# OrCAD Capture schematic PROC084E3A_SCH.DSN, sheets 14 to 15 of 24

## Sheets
14 10. PRG0 GB_ETHERNET RGMII 2: size C; title: PRG0 GB_ETHERNET RGMII 2
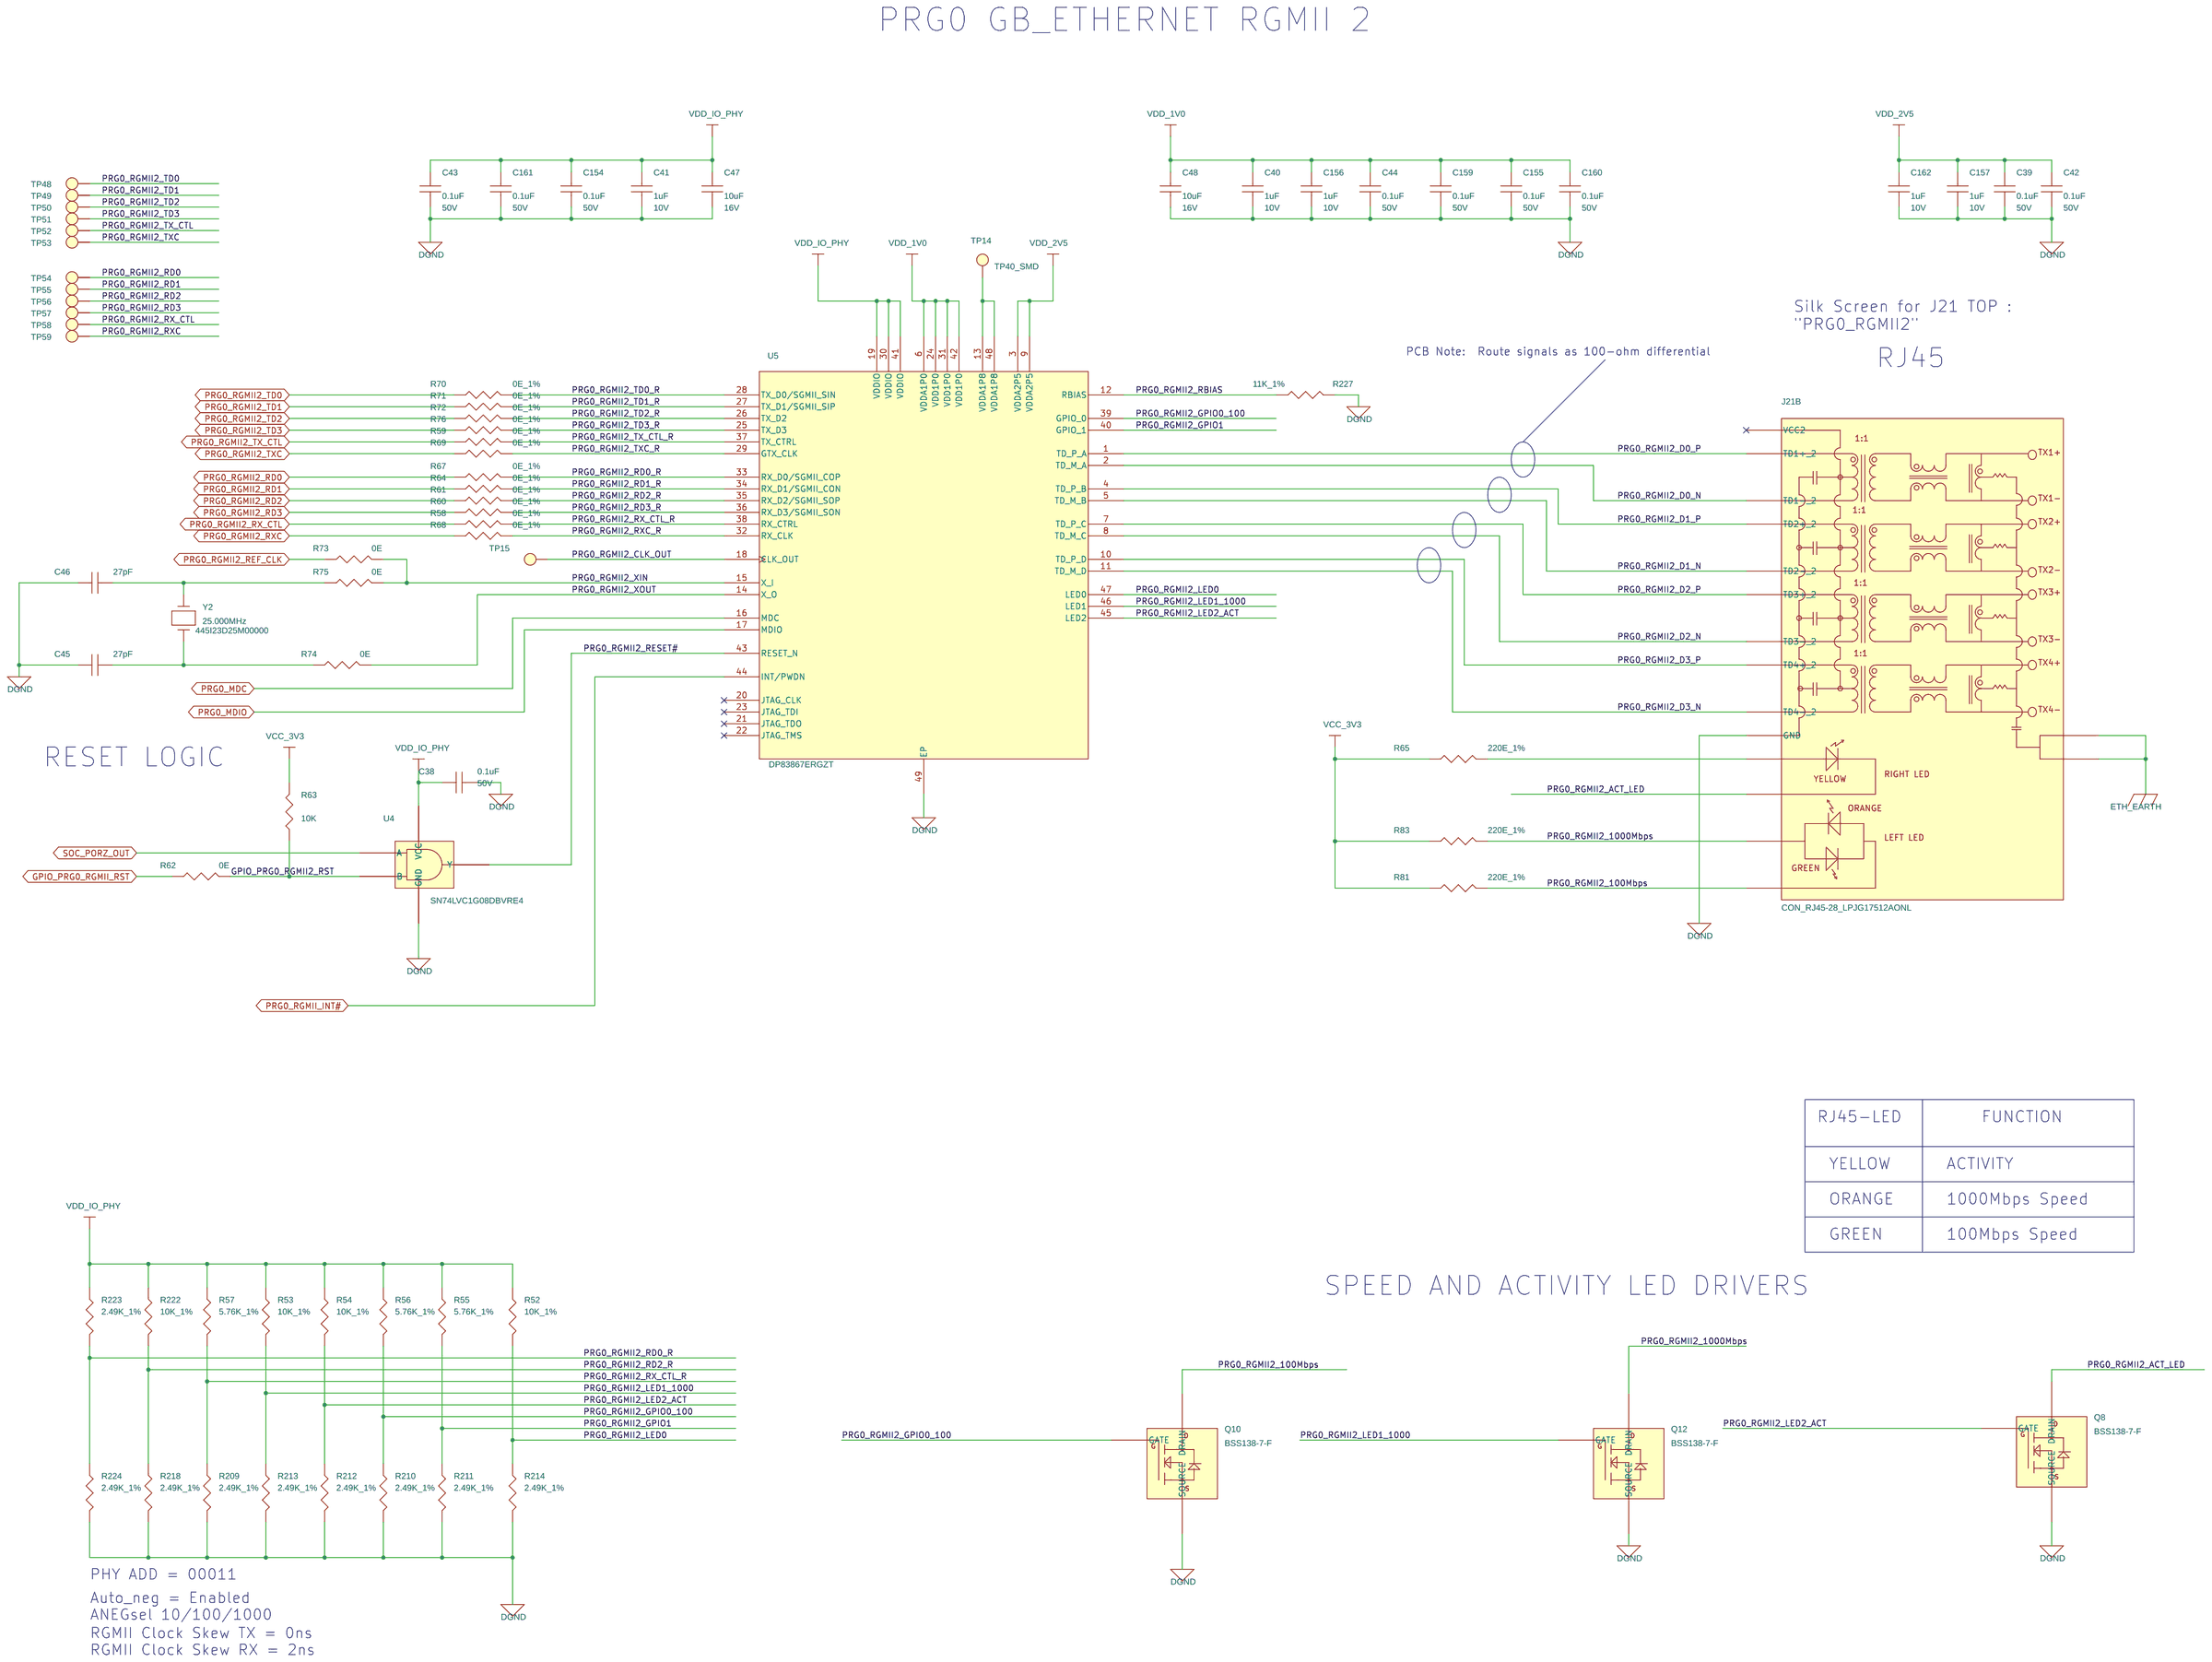
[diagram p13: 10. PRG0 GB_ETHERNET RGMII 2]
15 11. PRG1 GB_ETHERNET RGMII 1: size C; title: PRG1 GB_ETHERNET RGMII 1
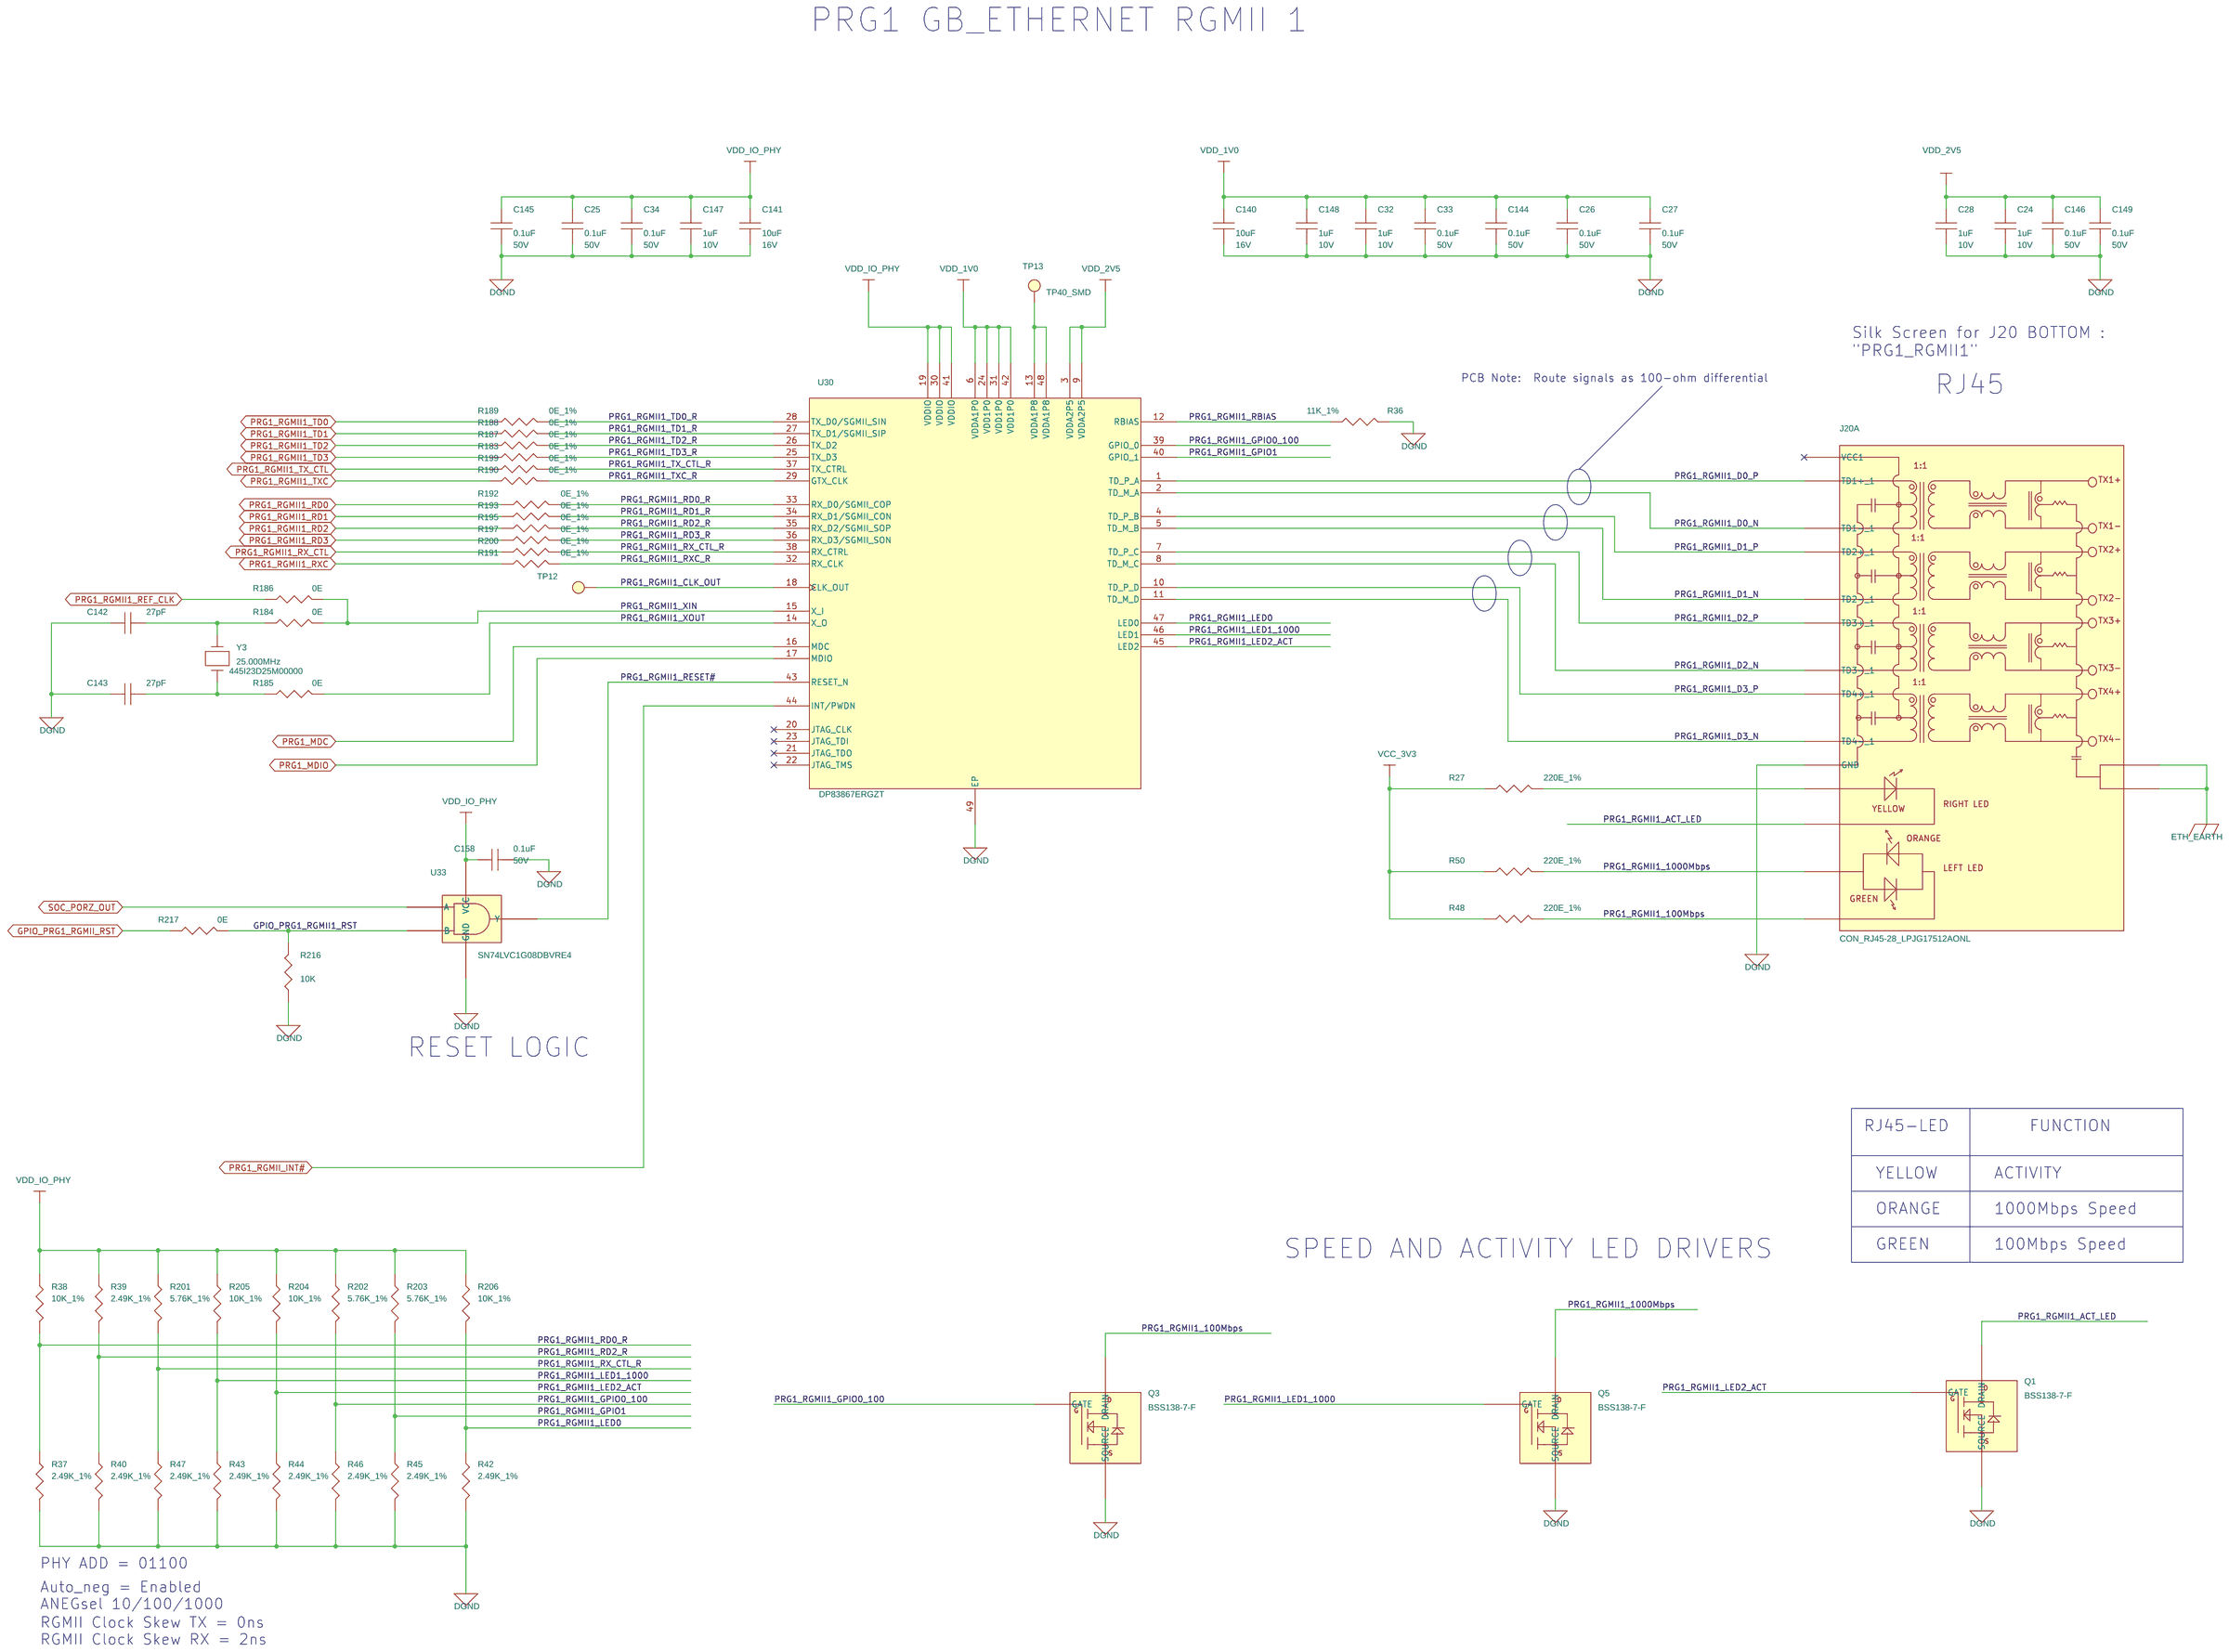
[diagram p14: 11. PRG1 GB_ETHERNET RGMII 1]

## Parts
sheet 09. PRG0 GB_ETHERNET RGMII 1
J21  CON_RJ45-28_LPJG17512AONL  [CON_RJ45-28_LPJG17512_S_R_T_25-3]  (sections A,B)
sheet 10. PRG0 GB_ETHERNET RGMII 2
C38  0.1uF  [CAP0402_0-75]
C39  0.1uF  [CAP0402_0-75]
C40  1uF  [CAP0402_0-75]
C41  1uF  [CAP0402_0-75]
C42  0.1uF  [CAP0402_0-75]
C43  0.1uF  [CAP0402_0-75]
C44  0.1uF  [CAP0402_0-75]
C45  27pF  [CAP0402_0-75]
C46  27pF  [CAP0402_0-75]
C47  10uF  [CAP0805_1-5]
C48  10uF  [CAP0805_1-5]
C154  0.1uF  [CAP0402_0-75]
C155  0.1uF  [CAP0402_0-75]
C156  1uF  [CAP0402_0-75]
C157  1uF  [CAP0402_0-75]
C159  0.1uF  [CAP0402_0-75]
C160  0.1uF  [CAP0402_0-75]
C161  0.1uF  [CAP0402_0-75]
C162  1uF  [CAP0402_0-75]
Q8  BSS138-7-F  [SOT23-123_1-1]
Q10  BSS138-7-F  [SOT23-123_1-1]
Q12  BSS138-7-F  [SOT23-123_1-1]
R52  10K_1%  [RES0402_0-5]
R53  10K_1%  [RES0402_0-5]
R54  10K_1%  [RES0402_0-5]
R55  5.76K_1%  [RES0402_0-5]
R56  5.76K_1%  [RES0402_0-5]
R57  5.76K_1%  [RES0402_0-5]
R58  0E_1%  [RES0402_0-5]
R59  0E_1%  [RES0402_0-5]
R60  0E_1%  [RES0402_0-5]
R61  0E_1%  [RES0402_0-5]
R62  0E  [RES0402_0-5]
R63  10K  [RES0402_0-5]
R64  0E_1%  [RES0402_0-5]
R65  220E_1%  [RES0402_0-5]
R67  0E_1%  [RES0402_0-5]
R68  0E_1%  [RES0402_0-5]
R69  0E_1%  [RES0402_0-5]
R70  0E_1%  [RES0402_0-5]
R71  0E_1%  [RES0402_0-5]
R72  0E_1%  [RES0402_0-5]
R73  0E  [RES0402_0-5]
R74  0E  [RES0402_0-5]
R75  0E  [RES0402_0-5]
R76  0E_1%  [RES0402_0-5]
R81  220E_1%  [RES0402_0-5]
R83  220E_1%  [RES0402_0-5]
R209  2.49K_1%  [RES0402_0-5]
R210  2.49K_1%  [RES0402_0-5]
R211  2.49K_1%  [RES0402_0-5]
R212  2.49K_1%  [RES0402_0-5]
R213  2.49K_1%  [RES0402_0-5]
R214  2.49K_1%  [RES0402_0-5]
R218  2.49K_1%  [RES0402_0-5]
R222  10K_1%  [RES0402_0-5]
R223  2.49K_1%  [RES0402_0-5]
R224  2.49K_1%  [RES0402_0-5]
R227  11K_1%  [RES0402_0-5]
TP14  TP40_SMD  [TP40_SMD]
TP15  TP40_SMD  [TP40_SMD]
TP48  TP20_SMD  [TP20_SMD]
TP49  TP20_SMD  [TP20_SMD]
TP50  TP20_SMD  [TP20_SMD]
TP51  TP20_SMD  [TP20_SMD]
TP52  TP20_SMD  [TP20_SMD]
TP53  TP20_SMD  [TP20_SMD]
TP54  TP20_SMD  [TP20_SMD]
TP55  TP20_SMD  [TP20_SMD]
TP56  TP20_SMD  [TP20_SMD]
TP57  TP20_SMD  [TP20_SMD]
TP58  TP20_SMD  [TP20_SMD]
TP59  TP20_SMD  [TP20_SMD]
U4  SN74LVC1G08DBVRE4  [SOT23-5]
U5  DP83867ERGZT  [VQFN48_19-68_285X285]
Y2  25.000MHz  [XTAL_ABM3_205X130_SMD_1-4]
sheet 11. PRG1 GB_ETHERNET RGMII 1
C24  1uF  [CAP0402_0-75]
C25  0.1uF  [CAP0402_0-75]
C26  0.1uF  [CAP0402_0-75]
C27  0.1uF  [CAP0402_0-75]
C28  1uF  [CAP0402_0-75]
C32  1uF  [CAP0402_0-75]
C33  0.1uF  [CAP0402_0-75]
C34  0.1uF  [CAP0402_0-75]
C140  10uF  [CAP0805_1-5]
C141  10uF  [CAP0805_1-5]
C142  27pF  [CAP0402_0-75]
C143  27pF  [CAP0402_0-75]
C144  0.1uF  [CAP0402_0-75]
C145  0.1uF  [CAP0402_0-75]
C146  0.1uF  [CAP0402_0-75]
C147  1uF  [CAP0402_0-75]
C148  1uF  [CAP0402_0-75]
C149  0.1uF  [CAP0402_0-75]
C158  0.1uF  [CAP0402_0-75]
Q1  BSS138-7-F  [SOT23-123_1-1]
Q3  BSS138-7-F  [SOT23-123_1-1]
Q5  BSS138-7-F  [SOT23-123_1-1]
R27  220E_1%  [RES0402_0-5]
R36  11K_1%  [RES0402_0-5]
R37  2.49K_1%  [RES0402_0-5]
R38  10K_1%  [RES0402_0-5]
R39  2.49K_1%  [RES0402_0-5]
R40  2.49K_1%  [RES0402_0-5]
R42  2.49K_1%  [RES0402_0-5]
R43  2.49K_1%  [RES0402_0-5]
R44  2.49K_1%  [RES0402_0-5]
R45  2.49K_1%  [RES0402_0-5]
R46  2.49K_1%  [RES0402_0-5]
R47  2.49K_1%  [RES0402_0-5]
R48  220E_1%  [RES0402_0-5]
R50  220E_1%  [RES0402_0-5]
R183  0E_1%  [RES0402_0-5]
R184  0E  [RES0402_0-5]
R185  0E  [RES0402_0-5]
R186  0E  [RES0402_0-5]
R187  0E_1%  [RES0402_0-5]
R188  0E_1%  [RES0402_0-5]
R189  0E_1%  [RES0402_0-5]
R190  0E_1%  [RES0402_0-5]
R191  0E_1%  [RES0402_0-5]
R192  0E_1%  [RES0402_0-5]
R193  0E_1%  [RES0402_0-5]
R195  0E_1%  [RES0402_0-5]
R197  0E_1%  [RES0402_0-5]
R199  0E_1%  [RES0402_0-5]
R200  0E_1%  [RES0402_0-5]
R201  5.76K_1%  [RES0402_0-5]
R202  5.76K_1%  [RES0402_0-5]
R203  5.76K_1%  [RES0402_0-5]
R204  10K_1%  [RES0402_0-5]
R205  10K_1%  [RES0402_0-5]
R206  10K_1%  [RES0402_0-5]
R216  10K  [RES0402_0-5]
R217  0E  [RES0402_0-5]
TP12  TP40_SMD  [TP40_SMD]
TP13  TP40_SMD  [TP40_SMD]
U30  DP83867ERGZT  [VQFN48_19-68_285X285]
U33  SN74LVC1G08DBVRE4  [SOT23-5]
Y3  25.000MHz  [XTAL_ABM3_205X130_SMD_1-4]
sheet 12. PRG1 GB_ETHERNET RGMII 2
J20  CON_RJ45-28_LPJG17512AONL  [CON_RJ45-28_LPJG17512_S_R_T_25-3]  (sections A,B)

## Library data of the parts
J20 J21 = CON_RJ45-28_LPJG17512AONL: CON JACK RJ45 28POS REGISTERED FEMALE RA TH; Chkd/date: MANIRAJA/010817; Crtd /date: MANIRAJA/010817; Custom_Duty: 24%; Customs_HS_Code: 85369090; Distributor_name: NA; Distributor_part_number: NA; Height: 25.30MM; Mfr_name: LINK-PP; Mfr_part_number: LPJG17512AONL; Mistral Part No: 150017080001-R; Package: THRU-HOLE; Part_type: CONNECTOR\JACK; Project: TI_SVB_DUT; RoHS: RoHS; Temperature: 0°C+70°C; Tolerance: NA; Voltage: NA; Wattage: NA; Weight: NA; Datasheet: Y:\MIS_DATABASE\DATASHEETS\CONNECTORS\LPJG17512AONL.PDF
C25-C27 C33 C34 C38 C39 C42 C44 C144-C146 C149 C154 C155 C158-C161 = CAP: CAP CERAMIC 0.1uF 50V 10% X7R 0402; Chkd/date: VASANTHA/281216; Crtd /date: CHAITHANYA/051011; Custom_Duty: 15%; Customs_HS_Code: 85322990; Distributor_name: DIGIKEY; Distributor_part_number: 445-173610-1-ND; Footprint Path: Y:\MIS_DATABASE\Library\ALTIUM_TOOL\PCB_FOOTPRINTS\Altium_Footprint_Lib.PcbLib; Height: 0.60MM; Library Path: Y:\MIS_DATABASE\Library\ALTIUM_TOOL\SCHEMATICS_PARTS\MS_DISCRETE_Library.schlib; Mfr_name: TDK CORPORATION; Mfr_part_number: C1005X7R1H104K050BE; Mistral Part No: 120011100014-R; Package: 0402; Part_type: CAPACITORS\CERAMIC; Project: VP-4000-BASE-BOARD; RoHS: RoHS; Temperature: -55°C+125°C; Tolerance: 10%; Voltage: 50V; Wattage: NA; Weight: 0.65mg; Datasheet: Y:\MIS_DATABASE\DATASHEETS\CAPACITORS\TDK_C-SER_FEB19.PDF
C24 C28 C32 C40 C41 C147 C148 C156 C157 C162 = CAP: CAP CERAMIC 1uF 10V 10% X5R 0402; Chkd/date: MANIRAJA/020718; Crtd /date: SARANYA/060514; Custom_Duty: 15%; Customs_HS_Code: 85322990; Distributor_name: DIGIKEY; Distributor_part_number: 478-4596-1-ND; Footprint Path: Y:\MIS_DATABASE\Library\ALTIUM_TOOL\PCB_FOOTPRINTS\Altium_Footprint_Lib.PcbLib; Height: 0.56MM; Library Path: Y:\MIS_DATABASE\Library\ALTIUM_TOOL\SCHEMATICS_PARTS\MS_DISCRETE_Library.schlib; Mfr_name: AVX CORPORATION; Mfr_part_number: 0402ZD105KAT2A; Mistral Part No: 120014050010-R; Package: 0402; Part_type: CAPACITORS\CERAMIC; Project: AEGIS GP BETA2; RoHS: RoHS; Temperature: -55°C+85°C; Tolerance: 10%; Voltage: 10V; Wattage: NA; Weight: 0.65mg; Datasheet: Y:\MIS_DATABASE\DATASHEETS\CAPACITORS\AVX_MLC.PDF
C43 = CAP: CAP CERAMIC 0.1uF 50V 10% X7R 0402; Chkd/date: VASANTHA/281216; Crtd /date: CHAITHANYA/051011; Custom_Duty: 15%; Customs_HS_Code: 85322990; Distributor_name: DIGIKEY; Distributor_part_number: 445-173610-1-ND; Footprint Path: Y:\MIS_DATABASE\Library\ALTIUM_TOOL\PCB_FOOTPRINTS\Altium_Footprint_Lib.PcbLib; Height: 0.60MM; Library Path: Y:\MIS_DATABASE\Library\ALTIUM_TOOL\SCHEMATICS_PARTS\MS_DISCRETE_Library.schlib; Mfr_name: TDK CORPORATION; Mfr_part_number: C1005X7R1H104K050BE; Mistral Part No: 120011100014-R; Package: 0402; Part_type: CAPACITORS\CERAMIC; Project: VP-4000-BASE-BOARD; RoHS: RoHS; SIGNAL_MODEL: INS23888586; Temperature: -55°C+125°C; Tolerance: 10%; Voltage: 50V; Wattage: NA; Weight: 0.65mg; Datasheet: Y:\MIS_DATABASE\DATASHEETS\CAPACITORS\TDK_C-SER_FEB19.PDF
C45 C46 C142 C143 = CAP: CAP CERAMIC 27pF 50V 5% C0G(NP0) 0402; Chkd/date: MAZHAR/241208; Crtd /date: GEETHA/090606; Custom_Duty: 15%; Customs_HS_Code: 85322990; Distributor_name: DIGIKEY; Distributor_part_number: 311-1019-1-ND; Footprint Path: Y:\MIS_DATABASE\Library\ALTIUM_TOOL\PCB_FOOTPRINTS\Altium_Footprint_Lib.PcbLib; Height: 0.55MM; Library Path: Y:\MIS_DATABASE\Library\ALTIUM_TOOL\SCHEMATICS_PARTS\MS_DISCRETE_Library.schlib; Mfr_name: YAGEO AMERICA; Mfr_part_number: CC0402JRNPO9BN270; Mistral Part No: 120014100024-R; Package: 0402; Part_type: CAPACITORS\CERAMIC; Project: PNAV; RoHS: RoHS; Temperature: -55°C+125°C; Tolerance: 5%; Voltage: 50V; Wattage: NA; Weight: 0.65mg; Datasheet: Y:\MIS_DATABASE\DATASHEETS\CAPACITORS\YACC-NPO.PDF
C47 C48 C140 C141 = CAP: CAP CERAMIC 10uF 16V 10% X5R 0805; Chkd/date: SHREESHAIL/220506; Crtd /date: MAZHAR/150506; Custom_Duty: 15%; Customs_HS_Code: 85322990; Distributor_name: DIGIKEY; Distributor_part_number: 490-3886-1-ND; Footprint Path: Y:\MIS_DATABASE\Library\ALTIUM_TOOL\PCB_FOOTPRINTS\Altium_Footprint_Lib.PcbLib; Height: 1.35MM; Library Path: Y:\MIS_DATABASE\Library\ALTIUM_TOOL\SCHEMATICS_PARTS\MS_DISCRETE_Library.schlib; Mfr_name: MURATA; Mfr_part_number: GRM21BR61C106KE15L; Mistral Part No: 120009030205-R; Package: 0805; Part_type: CAPACITORS\CERAMIC; Project: VOCERA; RoHS: RoHS; Temperature: -55°C+85°C; Tolerance: 10%; Voltage: 16V; Wattage: NA; Weight: 9.5mg; Datasheet: Y:\MIS_DATABASE\DATASHEETS\CAPACITORS\MURATA-GXX-SER_NOV17.PDF
Q1 Q3 Q5 Q8 Q10 Q12 = MOSFET_2N7002_SOT23: IC MOSFET N-CHANNEL 50V 200mA SOT23-123; Chkd/date: MANIRAJA/190618; Crtd /date: USMAN/240709; Custom_Duty: 15%; Customs_HS_Code: 85423100; Distributor_name: DIGIKEY; Distributor_part_number: BSS138-FDICT-ND; Footprint Path: Y:\MIS_DATABASE\Library\ALTIUM_TOOL\PCB_FOOTPRINTS\Altium_Footprint_Lib.PcbLib; Height: 1.10MM; Library Path: Y:\MIS_DATABASE\Library\ALTIUM_TOOL\SCHEMATICS_PARTS\MS_MOSFET_Library.schlib; Mfr_name: DIODES INC; Mistral Part No: 142009070019-R; Package: SOT23-123; Part_type: ICS\POWER\MOSFET; Project: KHAN_MAIN; RoHS: RoHS; Temperature: -55°C+150°C; Tolerance: NA; Voltage: 50V; Wattage: 300mW; Weight: 8mg; Datasheet: Y:\MIS_DATABASE\DATASHEETS\DISCRETES\TRANSISTORS_FETS\BSS138.PDF
R38 R52 R54 R204 R206 R222 = RESISTOR: RES 10K 1/16W 1% 0402; Assembly_Instruction: DNI; Chkd/date: VASANTHA/201216; Crtd /date: GEETHA/290506; Custom_Duty: 15%; Customs_HS_Code: 85332119; Distributor_name: DIGIKEY; Distributor_part_number: 311-10.0KLRTR-ND; Footprint Path: Y:\MIS_DATABASE\Library\ALTIUM_TOOL\PCB_FOOTPRINTS\Altium_Footprint_Lib.PcbLib; Height: 0.40MM; Library Path: Y:\MIS_DATABASE\Library\ALTIUM_TOOL\SCHEMATICS_PARTS\MS_DISCRETE_Library.schlib; Mfr_name: YAGEO AMERICA; Mfr_part_number: RC0402FR-0710KL; Mistral Part No: 110015090015-R; Package: 0402; Part_type: RESISTORS\FIXED; Project: VOCERA; RoHS: RoHS; Temperature: -55°C+155°C; Tolerance: 1%; Voltage: NA; Wattage: 1/16W; Weight: 0.65mg; Datasheet: Y:\MIS_DATABASE\DATASHEETS\RESISTORS\RCXXXXL-SER_MAR18.PDF
R53 R205 = RESISTOR: RES 10K 1/16W 1% 0402; Chkd/date: VASANTHA/201216; Crtd /date: GEETHA/290506; Custom_Duty: 15%; Customs_HS_Code: 85332119; Distributor_name: DIGIKEY; Distributor_part_number: 311-10.0KLRTR-ND; Footprint Path: Y:\MIS_DATABASE\Library\ALTIUM_TOOL\PCB_FOOTPRINTS\Altium_Footprint_Lib.PcbLib; Height: 0.40MM; Library Path: Y:\MIS_DATABASE\Library\ALTIUM_TOOL\SCHEMATICS_PARTS\MS_DISCRETE_Library.schlib; Mfr_name: YAGEO AMERICA; Mfr_part_number: RC0402FR-0710KL; Mistral Part No: 110015090015-R; Package: 0402; Part_type: RESISTORS\FIXED; Project: VOCERA; RoHS: RoHS; Temperature: -55°C+155°C; Tolerance: 1%; Voltage: NA; Wattage: 1/16W; Weight: 0.65mg; Datasheet: Y:\MIS_DATABASE\DATASHEETS\RESISTORS\RCXXXXL-SER_MAR18.PDF
R55 R56 R202 R203 = RESISTOR: RES 5.76K 1/10W 1% 0402; Assembly_Instruction: DNI; Chkd/date: MAZHAR/150709; Crtd /date: USMAN/220808; Custom_Duty: 15%; Customs_HS_Code: 85332119; Distributor_name: DIGIKEY; Distributor_part_number: P5.76KLCT-ND; Footprint Path: Y:\MIS_DATABASE\Library\ALTIUM_TOOL\PCB_FOOTPRINTS\Altium_Footprint_Lib.PcbLib; Height: 0.40MM; Library Path: Y:\MIS_DATABASE\Library\ALTIUM_TOOL\SCHEMATICS_PARTS\MS_DISCRETE_Library.schlib; Mfr_name: PANASONIC-ECG; Mfr_part_number: ERJ-2RKF5761X; Mistral Part No: 110009030945-R; Package: 0402; Part_type: RESISTORS\FIXED; Project: CPB; RoHS: RoHS; Temperature: -55°C+155°C; Tolerance: 1%; Voltage: NA; Wattage: 1/10W; Weight: 0.8mg; Datasheet: Y:\MIS_DATABASE\DATASHEETS\RESISTORS\PAN-ERJSER_NOV17.PDF
R57 R201 = RESISTOR: RES 5.76K 1/10W 1% 0402; Chkd/date: MAZHAR/150709; Crtd /date: USMAN/220808; Custom_Duty: 15%; Customs_HS_Code: 85332119; Distributor_name: DIGIKEY; Distributor_part_number: P5.76KLCT-ND; Footprint Path: Y:\MIS_DATABASE\Library\ALTIUM_TOOL\PCB_FOOTPRINTS\Altium_Footprint_Lib.PcbLib; Height: 0.40MM; Library Path: Y:\MIS_DATABASE\Library\ALTIUM_TOOL\SCHEMATICS_PARTS\MS_DISCRETE_Library.schlib; Mfr_name: PANASONIC-ECG; Mfr_part_number: ERJ-2RKF5761X; Mistral Part No: 110009030945-R; Package: 0402; Part_type: RESISTORS\FIXED; Project: CPB; RoHS: RoHS; Temperature: -55°C+155°C; Tolerance: 1%; Voltage: NA; Wattage: 1/10W; Weight: 0.8mg; Datasheet: Y:\MIS_DATABASE\DATASHEETS\RESISTORS\PAN-ERJSER_NOV17.PDF
R58 R60 R61 R64 R67 R68 R191-R193 R195 R197 R200 = RESISTOR: RES 0E 1/16W 1% 0402; Chkd/date: MAZHAR/220709; Crtd /date: USMAN/270109; Custom_Duty: 15%; Customs_HS_Code: 85332119; Distributor_name: DIGIKEY; Distributor_part_number: 311-0.0LRCT-ND; Footprint Path: Y:\MIS_DATABASE\Library\ALTIUM_TOOL\PCB_FOOTPRINTS\Altium_Footprint_Lib.PcbLib; Height: 0.40MM; Library Path: Y:\MIS_DATABASE\Library\ALTIUM_TOOL\SCHEMATICS_PARTS\MS_DISCRETE_Library.schlib; Mfr_name: YAGEO AMERICA; Mfr_part_number: RC0402FR-070RL; Mistral Part No: 110009030085-R; Package: 0402; Part_type: RESISTORS\FIXED; Project: OMAP_EVM; RoHS: RoHS; SIGNAL_MODEL: RESISTOR_RES0402_22E_1%_22E_1%; Temperature: -55°C+155°C; Tolerance: 1%; Voltage: NA; Wattage: 1/16W; Weight: 0.65mg; Datasheet: Y:\MIS_DATABASE\DATASHEETS\RESISTORS\RCXXXXL-SER_MAR18.PDF
R59 R69-R72 R76 R183 R187-R190 R199 = RESISTOR: RES 0E 1/16W 1% 0402; Chkd/date: MAZHAR/220709; Crtd /date: USMAN/270109; Custom_Duty: 15%; Customs_HS_Code: 85332119; Distributor_name: DIGIKEY; Distributor_part_number: 311-0.0LRCT-ND; Footprint Path: Y:\MIS_DATABASE\Library\ALTIUM_TOOL\PCB_FOOTPRINTS\Altium_Footprint_Lib.PcbLib; Height: 0.40MM; Library Path: Y:\MIS_DATABASE\Library\ALTIUM_TOOL\SCHEMATICS_PARTS\MS_DISCRETE_Library.schlib; Mfr_name: YAGEO AMERICA; Mfr_part_number: RC0402FR-070RL; Mistral Part No: 110009030085-R; Package: 0402; Part_type: RESISTORS\FIXED; Project: OMAP_EVM; RoHS: RoHS; SIGNAL_MODEL: INS23888567; Temperature: -55°C+155°C; Tolerance: 1%; Voltage: NA; Wattage: 1/16W; Weight: 0.65mg; Datasheet: Y:\MIS_DATABASE\DATASHEETS\RESISTORS\RCXXXXL-SER_MAR18.PDF
R62 R74 R75 R184 R185 R217 = RESISTOR: RES 0E 1/10W JUMPER 0402; Chkd/date: MANIRAJA/290318; Crtd /date: ALVY/270318; Custom_Duty: 15%; Customs_HS_Code: 85332119; Distributor_name: DIGIKEY; Distributor_part_number: MCS0402-0.0-ZZCT-ND; Footprint Path: Y:\MIS_DATABASE\Library\ALTIUM_TOOL\PCB_FOOTPRINTS\Altium_Footprint_Lib.PcbLib; Height: 0.37MM; Library Path: Y:\MIS_DATABASE\Library\ALTIUM_TOOL\SCHEMATICS_PARTS\MS_DISCRETE_Library.schlib; Mfr_name: VISHAY; Mfr_part_number: MCS04020Z0000ZE000; Mistral Part No: 110018030052-R; Package: 0402; Part_type: RESISTORS\FIXED; Project: DRDL_ITS2-SC; RoHS: RoHS; SIGNAL_MODEL: INS23888567; Temperature: -55°C+155°C; Tolerance: NA; Voltage: NA; Wattage: 1/10W; Weight: 0.65mg; Datasheet: Y:\MIS_DATABASE\DATASHEETS\RESISTORS\MCTXXXXC-SER.PDF
R63 = RESISTOR: RES 10K 1/16W 5% 0402; Chkd/date: VASANTHA/061216; Crtd /date: MAZHAR/230805; Custom_Duty: 15%; Customs_HS_Code: 85332119; Distributor_name: DIGIKEY; Distributor_part_number: 311-10KJRCT-ND; Footprint Path: Y:\MIS_DATABASE\Library\ALTIUM_TOOL\PCB_FOOTPRINTS\Altium_Footprint_Lib.PcbLib; Height: 0.40MM; Library Path: Y:\MIS_DATABASE\Library\ALTIUM_TOOL\SCHEMATICS_PARTS\MS_DISCRETE_Library.schlib; Mfr_name: YAGEO AMERICA; Mfr_part_number: RC0402JR-0710KL; Mistral Part No: 110011060021-R; Package: 0402; Part_type: RESISTORS\FIXED; Project: HSE; RoHS: RoHS; Temperature: -55°C+155°C; Tolerance: 5%; Voltage: NA; Wattage: 1/16W; Weight: 0.65mg; Datasheet: Y:\MIS_DATABASE\DATASHEETS\RESISTORS\RCXXXXL-SER_MAR18.PDF
R27 R48 R50 R65 R81 R83 = RESISTOR: RES 220E 1/10W 1% 0402; Chkd/date: MANIRAJA/130617; Crtd /date: BAVISH/260711; Custom_Duty: 15%; Customs_HS_Code: 85332119; Distributor_name: DIGIKEY; Distributor_part_number: P220LCT-ND; Footprint Path: Y:\MIS_DATABASE\Library\ALTIUM_TOOL\PCB_FOOTPRINTS\Altium_Footprint_Lib.PcbLib; Height: 0.40MM; Library Path: Y:\MIS_DATABASE\Library\ALTIUM_TOOL\SCHEMATICS_PARTS\MS_DISCRETE_Library.schlib; Mfr_name: PANASONIC-ECG; Mfr_part_number: ERJ-2RKF2200X; Mistral Part No: 110011070017-R; Package: 0402; Part_type: RESISTORS\FIXED; Project: LSM; RoHS: RoHS; Temperature: -55°C+155°C; Tolerance: 1%; Voltage: NA; Wattage: 1/10W; Weight: 0.8mg; Datasheet: Y:\MIS_DATABASE\DATASHEETS\RESISTORS\PAN-ERJSER_NOV17.PDF
R73 R186 = RESISTOR: RES 0E 1/10W JUMPER 0402; Assembly_Instruction: DNI; Chkd/date: MANIRAJA/290318; Crtd /date: ALVY/270318; Custom_Duty: 15%; Customs_HS_Code: 85332119; Distributor_name: DIGIKEY; Distributor_part_number: MCS0402-0.0-ZZCT-ND; Footprint Path: Y:\MIS_DATABASE\Library\ALTIUM_TOOL\PCB_FOOTPRINTS\Altium_Footprint_Lib.PcbLib; Height: 0.37MM; Library Path: Y:\MIS_DATABASE\Library\ALTIUM_TOOL\SCHEMATICS_PARTS\MS_DISCRETE_Library.schlib; Mfr_name: VISHAY; Mfr_part_number: MCS04020Z0000ZE000; Mistral Part No: 110018030052-R; Package: 0402; Part_type: RESISTORS\FIXED; Project: DRDL_ITS2-SC; RoHS: RoHS; SIGNAL_MODEL: INS23888567; Temperature: -55°C+155°C; Tolerance: NA; Voltage: NA; Wattage: 1/10W; Weight: 0.65mg; Datasheet: Y:\MIS_DATABASE\DATASHEETS\RESISTORS\MCTXXXXC-SER.PDF
R39 R43 R47 R209 R213 R223 = RESISTOR: RES 2.49K 1/16W 1% 0402; Chkd/date: VASANTHA/270516; Crtd /date: VASANTHA/270516; Custom_Duty: 15%; Customs_HS_Code: 85332119; Distributor_name: DIGIKEY; Distributor_part_number: 311-2.49KLRCT-ND; Footprint Path: Y:\MIS_DATABASE\Library\ALTIUM_TOOL\PCB_FOOTPRINTS\Altium_Footprint_Lib.PcbLib; Height: 0.40MM; Library Path: Y:\MIS_DATABASE\Library\ALTIUM_TOOL\SCHEMATICS_PARTS\MS_DISCRETE_Library.schlib; Mfr_name: YAGEO AMERICA; Mfr_part_number: RC0402FR-072K49L; Mistral Part No: 110016050020-R; Package: 0402; Part_type: RESISTORS\FIXED; Project: TMDXCSKCC; RoHS: RoHS; Temperature: -55°C+155°C; Tolerance: 1%; Voltage: NA; Wattage: 1/16W; Weight: 0.65mg; Datasheet: Y:\MIS_DATABASE\DATASHEETS\RESISTORS\RCXXXXL-SER_MAR18.PDF
R37 R40 R42 R44-R46 R210-R212 R214 R218 R224 = RESISTOR: RES 2.49K 1/16W 1% 0402; Assembly_Instruction: DNI; Chkd/date: VASANTHA/270516; Crtd /date: VASANTHA/270516; Custom_Duty: 15%; Customs_HS_Code: 85332119; Distributor_name: DIGIKEY; Distributor_part_number: 311-2.49KLRCT-ND; Footprint Path: Y:\MIS_DATABASE\Library\ALTIUM_TOOL\PCB_FOOTPRINTS\Altium_Footprint_Lib.PcbLib; Height: 0.40MM; Library Path: Y:\MIS_DATABASE\Library\ALTIUM_TOOL\SCHEMATICS_PARTS\MS_DISCRETE_Library.schlib; Mfr_name: YAGEO AMERICA; Mfr_part_number: RC0402FR-072K49L; Mistral Part No: 110016050020-R; Package: 0402; Part_type: RESISTORS\FIXED; Project: TMDXCSKCC; RoHS: RoHS; Temperature: -55°C+155°C; Tolerance: 1%; Voltage: NA; Wattage: 1/16W; Weight: 0.65mg; Datasheet: Y:\MIS_DATABASE\DATASHEETS\RESISTORS\RCXXXXL-SER_MAR18.PDF
R36 R227 = RESISTOR: RES 11K 1/16W 1% 0402; Chkd/date: VASANTHA/251115; Crtd /date: VASANTHA/251115; Custom_Duty: 15%; Customs_HS_Code: 85332119; Distributor_name: DIGIKEY; Distributor_part_number: 311-11.0KLRCT-ND; Footprint Path: Y:\MIS_DATABASE\Library\ALTIUM_TOOL\PCB_FOOTPRINTS\Altium_Footprint_Lib.PcbLib; Height: 0.40MM; Library Path: Y:\MIS_DATABASE\Library\ALTIUM_TOOL\SCHEMATICS_PARTS\MS_DISCRETE_Library.schlib; Mfr_name: YAGEO AMERICA; Mfr_part_number: RC0402FR-0711KL; Mistral Part No: 110015110012-R; Package: 0402; Part_type: RESISTORS\FIXED; Project: TI_VLAN_SWITCH; RoHS: RoHS; Temperature: -55°C+155°C; Tolerance: 1%; Voltage: NA; Wattage: 1/16W; Weight: 0.65mg; Datasheet: Y:\MIS_DATABASE\DATASHEETS\RESISTORS\RCXXXXL-SER_MAR18.PDF
TP12-TP15 = TESTPOINT: TESTPOINT CIR 40 SMD; Chkd/date: MAZHAR/190505; Crtd /date: MAZHAR/190505; Distributor_name: NA; Distributor_part_number: NA; Footprint Path: Y:\MIS_DATABASE\Library\ALTIUM_TOOL\PCB_FOOTPRINTS\Altium_Footprint_Lib.PcbLib; Height: NA; Library Path: Y:\MIS_DATABASE\Library\ALTIUM_TOOL\SCHEMATICS_PARTS\MS_DISCRETE_Library.schlib; MECHANICAL 3D STEP FILE: NA; Mfr_name: LOCAL; Mistral Part No: 130009030933; Package: SMD; Project: RAINIER-3; RoHS: NA; Temperature: NA; Tolerance: NA; Voltage: NA; Wattage: NA; Weight: NA; Datasheet: NA
TP48-TP59 = TESTPOINT: TESTPOINT CIR 20 SMD; Chkd/date: SHREESHAIL/171006; Crtd /date: MAZHAR/171006; Custom_Duty: NA; Customs_HS_Code: NA; Distributor_name: NA; Distributor_part_number: NA; Footprint Path: Y:\MIS_DATABASE\Library\ALTIUM_TOOL\PCB_FOOTPRINTS\Altium_Footprint_Lib.PcbLib; Height: NA; Library Path: Y:\MIS_DATABASE\Library\ALTIUM_TOOL\SCHEMATICS_PARTS\MS_DISCRETE_Library.schlib; MECHANICAL 3D STEP FILE: NA; Mfr_name: LOCAL; Mistral Part No: NA; Package: SMD; Project: BT MODULE_CSRBC04; RoHS: NA; Temperature: NA; Tolerance: NA; Voltage: NA; Wattage: NA; Weight: NA; Datasheet: NA
U4 U33 = SN74LVC1G08DBVRE4_SOT23-5: IC SINGLE 2-INPUT POSITIVE AND GATE SOT23-5; Chkd/date: SUHAS/221010; Crtd /date: USMAN/151008; Custom_Duty: 15%; Customs_HS_Code: 85423100; Distributor_name: DIGIKEY; Distributor_part_number: SN74LVC1G08DBVRE4-ND; Height: 1.45MM; Mfr_name: TEXAS INSTRUMENTS; Mistral Part No: 141009060026-R; Part_type: ICS\DIGITAL\GATES; Project: KHAN_MAIN; RoHS: Sb/ Br FREE; Temperature: -40°C+85°C; Datasheet: Y:\MIS_DATABASE\DATASHEETS\ICS\DIGITAL\GATES\SN74LVC1G08.PDF
U5 U30 = DP83867ERGZT_VQFN48: IC SMALL FORM FACTOR 10/100/1000 Mb/s ETHERNET PHY LAYER TRANSCEIVER VQFN48; Chkd/date: VASANTHA/251115; Crtd /date: VASANTHA/251115; Custom_Duty: 15%; Customs_HS_Code: 85423100; Distributor_name: DIGIKEY; Distributor_part_number: 296-43254-1-ND; Height: 1.00MM; Mfr_name: TEXAS INSTRUMENTS; Mistral Part No: 143015110004-R; Package: VQFN48; Part_type: ICS\TELECOM\TRANSCEIVER; Project: TI_VLAN_SWITCH; RoHS: RoHS; Temperature: -40°C+105°C; Tolerance: NA; Voltage: NA; Wattage: NA; Weight: NA; Datasheet: Y:\MIS_DATABASE\DATASHEETS\ICS\DIGITAL\BUSTRANSCEIVER\DP83867.PDF
Y2 Y3 = CRY: CRY 25.000MHz 18pF SMD; Chkd/date: VASANTHA/110316; Crtd /date: JEBRAN/090216; Custom_Duty: 24%; Customs_HS_Code: 85439000; Distributor_name: DIGIKEY; Distributor_part_number: CTX1175CT-ND; Footprint Path: Y:\MIS_DATABASE\Library\ALTIUM_TOOL\PCB_FOOTPRINTS\Altium_Footprint_Lib.PcbLib; Height: 1.35MM; Library Path: Y:\MIS_DATABASE\Library\ALTIUM_TOOL\SCHEMATICS_PARTS\MS_DISCRETE_Library.schlib; Mfr_name: CTS; Mfr_part_number: 445I23D25M00000; Mistral Part No: 130016020016-R; Package: SMD; Part_type: CRYSTAL; Project: PDI_MINIPCB; RoHS: RoHS; Temperature: -40°C+85°C; Tolerance: NA; Voltage: NA; Wattage: NA; Weight: 50mg; Datasheet: Y:\MIS_DATABASE\DATASHEETS\MISC\CRY_OSC\445.PDF
R216 = RESISTOR: RES 10K 1/16W 5% 0402; Assembly_Instruction: DNI; Chkd/date: VASANTHA/061216; Crtd /date: MAZHAR/230805; Custom_Duty: 15%; Customs_HS_Code: 85332119; Distributor_name: DIGIKEY; Distributor_part_number: 311-10KJRCT-ND; Footprint Path: Y:\MIS_DATABASE\Library\ALTIUM_TOOL\PCB_FOOTPRINTS\Altium_Footprint_Lib.PcbLib; Height: 0.40MM; Library Path: Y:\MIS_DATABASE\Library\ALTIUM_TOOL\SCHEMATICS_PARTS\MS_DISCRETE_Library.schlib; Mfr_name: YAGEO AMERICA; Mfr_part_number: RC0402JR-0710KL; Mistral Part No: 110011060021-R; Package: 0402; Part_type: RESISTORS\FIXED; Project: HSE; RoHS: RoHS; Temperature: -55°C+155°C; Tolerance: 5%; Voltage: NA; Wattage: 1/16W; Weight: 0.65mg; Datasheet: Y:\MIS_DATABASE\DATASHEETS\RESISTORS\RCXXXXL-SER_MAR18.PDF

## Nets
DGND: C24.2 C25.2 C26.2 C27.2 C28.2 C32.2 C33.2 C34.2 C38.2 C39.2 C40.2 C41.2 C42.2 C43.2 C44.2 C45.1 C46.1 C47.2 C48.2 C140.2 C141.2 C142.1 C143.1 C144.2 C145.2 C146.2 C147.2 C148.2 C149.2 C154.2 C155.2 C156.2 C157.2 C158.2 C159.2 C160.2 C161.2 C162.2 J20.A10(GND) J21.B10(GND) Q1.2(SOURCE) Q3.2(SOURCE) Q5.2(SOURCE) Q8.2(SOURCE) Q10.2(SOURCE) Q12.2(SOURCE) R36.1 R37.2 R40.2 R42.2 R43.2 R44.2 R45.2 R46.2 R47.2 R209.2 R210.2 R211.2 R212.2 R213.2 R214.2 R216.1 R218.2 R224.2 R227.1 U4.3(GND) U5.49(EP) U30.49(EP) U33.3(GND) ; also on sheet 1 2 3 8 9 10 11 12 13 16 17 18 19 20 21 22 23 24
VCC_3V3: R27.1 R48.1 R50.1 R63.2 R65.1 R81.1 R83.1 ; also on sheet 1 2 3 8 9 10 11 12 13 16 17 18 19 20 22 23 24
VDD_1V0: C26.1 C27.1 C32.1 C33.1 C40.1 C44.1 C48.1 C140.1 C144.1 C148.1 C155.1 C156.1 C159.1 C160.1 U5.6(VDDA1P0) U5.24(VDD1P0) U5.31(VDD1P0) U5.42(VDD1P0) U30.6(VDDA1P0) U30.24(VDD1P0) U30.31(VDD1P0) U30.42(VDD1P0) ; also on sheet 13 16 23
VDD_2V5: C24.1 C28.1 C39.1 C42.1 C146.1 C149.1 C157.1 C162.1 U5.3(VDDA2P5) U5.9(VDDA2P5) U30.3(VDDA2P5) U30.9(VDDA2P5) ; also on sheet 13 16 23
VDD_IO_PHY: C25.1 C34.1 C38.1 C41.1 C43.1 C47.1 C141.1 C145.1 C147.1 C154.1 C158.1 C161.1 R38.1 R39.1 R52.1 R53.1 R54.1 R55.1 R56.1 R57.1 R201.1 R202.1 R203.1 R204.1 R205.1 R206.1 R222.1 R223.1 U4.5(VCC) U5.19(VDDIO) U5.30(VDDIO) U5.41(VDDIO) U30.19(VDDIO) U30.30(VDDIO) U30.41(VDDIO) U33.5(VCC) ; also on sheet 12 13 16
ETH_EARTH: J20.SH1 J20.SH2 J21.SH3 J21.SH4 ; also on sheet 13 16 22
GPIO_PRG0_RGMII2_RST: R62.2 R63.1 U4.2(B)
GPIO_PRG0_RGMII_RST: R62.1 ; also on sheet 8 13
GPIO_PRG1_RGMII1_RST: R216.2 R217.2 U33.2(B)
GPIO_PRG1_RGMII_RST: R217.1 ; also on sheet 8 16
PRG0_MDC: U5.16(MDC) ; also on sheet 12 13
PRG0_MDIO: U5.17(MDIO) ; also on sheet 12 13
PRG0_RGMII2_100Mbps: J21.B13 Q10.3(DRAIN) R81.2
PRG0_RGMII2_1000Mbps: J21.B14 Q12.3(DRAIN) R83.2
PRG0_RGMII2_ACT_LED: J21.B11 Q8.3(DRAIN)
PRG0_RGMII2_CLK_OUT: TP15.1(TP) U5.18(CLK_OUT)
PRG0_RGMII2_D0_N: J21.B2(TD1-_2) U5.2(TD_M_A)
PRG0_RGMII2_D0_P: J21.B1(TD1+_2) U5.1(TD_P_A)
PRG0_RGMII2_D1_N: J21.B4(TD2-_2) U5.5(TD_M_B)
PRG0_RGMII2_D1_P: J21.B3(TD2+_2) U5.4(TD_P_B)
PRG0_RGMII2_D2_N: J21.B6(TD3-_2) U5.8(TD_M_C)
PRG0_RGMII2_D2_P: J21.B5(TD3+_2) U5.7(TD_P_C)
PRG0_RGMII2_D3_N: J21.B8(TD4-_2) U5.11(TD_M_D)
PRG0_RGMII2_D3_P: J21.B7(TD4+_2) U5.10(TD_P_D)
PRG0_RGMII2_GPIO0_100: Q10.1(GATE) R56.2 R210.1 U5.39(GPIO_0)
PRG0_RGMII2_GPIO1: R55.2 R211.1 U5.40(GPIO_1)
PRG0_RGMII2_LED0: R52.2 R214.1 U5.47(LED0)
PRG0_RGMII2_LED1_1000: Q12.1(GATE) R53.2 R213.1 U5.46(LED1)
PRG0_RGMII2_LED2_ACT: Q8.1(GATE) R54.2 R212.1 U5.45(LED2)
PRG0_RGMII2_RBIAS: R227.2 U5.12(RBIAS)
PRG0_RGMII2_RD0: R67.1 TP54.1(TP) ; also on sheet 8
PRG0_RGMII2_RD0_R: R67.2 R223.2 R224.1 U5.33(RX_D0/SGMII_COP)
PRG0_RGMII2_RD1: R64.1 TP55.1(TP) ; also on sheet 8
PRG0_RGMII2_RD1_R: R64.2 U5.34(RX_D1/SGMII_CON)
PRG0_RGMII2_RD2: R61.1 TP56.1(TP) ; also on sheet 8
PRG0_RGMII2_RD2_R: R61.2 R218.1 R222.2 U5.35(RX_D2/SGMII_SOP)
PRG0_RGMII2_RD3: R60.1 TP57.1(TP) ; also on sheet 8
PRG0_RGMII2_RD3_R: R60.2 U5.36(RX_D3/SGMII_SON)
PRG0_RGMII2_REF_CLK: R73.1 ; also on sheet 9
PRG0_RGMII2_RESET#: U4.4(Y) U5.43(RESET_N)
PRG0_RGMII2_RX_CTL: R58.1 TP58.1(TP) ; also on sheet 8
PRG0_RGMII2_RX_CTL_R: R57.2 R58.2 R209.1 U5.38(RX_CTRL)
PRG0_RGMII2_RXC: R68.1 TP59.1(TP) ; also on sheet 8
PRG0_RGMII2_RXC_R: R68.2 U5.32(RX_CLK)
PRG0_RGMII2_TD0: R70.1 TP48.1(TP) ; also on sheet 8
PRG0_RGMII2_TD0_R: R70.2 U5.28(TX_D0/SGMII_SIN)
PRG0_RGMII2_TD1: R71.1 TP49.1(TP) ; also on sheet 8
PRG0_RGMII2_TD1_R: R71.2 U5.27(TX_D1/SGMII_SIP)
PRG0_RGMII2_TD2: R72.1 TP50.1(TP) ; also on sheet 8
PRG0_RGMII2_TD2_R: R72.2 U5.26(TX_D2)
PRG0_RGMII2_TD3: R76.1 TP51.1(TP) ; also on sheet 8
PRG0_RGMII2_TD3_R: R76.2 U5.25(TX_D3)
PRG0_RGMII2_TX_CTL: R59.1 TP52.1(TP) ; also on sheet 8
PRG0_RGMII2_TX_CTL_R: R59.2 U5.37(TX_CTRL)
PRG0_RGMII2_TXC: R69.1 TP53.1(TP) ; also on sheet 8
PRG0_RGMII2_TXC_R: R69.2 U5.29(GTX_CLK)
PRG0_RGMII2_XIN: R73.2 R75.2 U5.15(X_I)
PRG0_RGMII2_XOUT: R74.2 U5.14(X_O)
PRG0_RGMII_INT#: U5.44(INT/PWDN) ; also on sheet 8 13
PRG1_MDC: U30.16(MDC) ; also on sheet 12 16
PRG1_MDIO: U30.17(MDIO) ; also on sheet 12 16
PRG1_RGMII1_100Mbps: J20.A13 Q3.3(DRAIN) R48.2
PRG1_RGMII1_1000Mbps: J20.A14 Q5.3(DRAIN) R50.2
PRG1_RGMII1_ACT_LED: J20.A11 Q1.3(DRAIN)
PRG1_RGMII1_CLK_OUT: TP12.1(TP) U30.18(CLK_OUT)
PRG1_RGMII1_D0_N: J20.A2(TD1-_1) U30.2(TD_M_A)
PRG1_RGMII1_D0_P: J20.A1(TD1+_1) U30.1(TD_P_A)
PRG1_RGMII1_D1_N: J20.A4(TD2-_1) U30.5(TD_M_B)
PRG1_RGMII1_D1_P: J20.A3(TD2+_1) U30.4(TD_P_B)
PRG1_RGMII1_D2_N: J20.A6(TD3-_1) U30.8(TD_M_C)
PRG1_RGMII1_D2_P: J20.A5(TD3+_1) U30.7(TD_P_C)
PRG1_RGMII1_D3_N: J20.A8(TD4-_1) U30.11(TD_M_D)
PRG1_RGMII1_D3_P: J20.A7(TD4+_1) U30.10(TD_P_D)
PRG1_RGMII1_GPIO0_100: Q3.1(GATE) R46.1 R202.2 U30.39(GPIO_0)
PRG1_RGMII1_GPIO1: R45.1 R203.2 U30.40(GPIO_1)
PRG1_RGMII1_LED0: R42.1 R206.2 U30.47(LED0)
PRG1_RGMII1_LED1_1000: Q5.1(GATE) R43.1 R205.2 U30.46(LED1)
PRG1_RGMII1_LED2_ACT: Q1.1(GATE) R44.1 R204.2 U30.45(LED2)
PRG1_RGMII1_RBIAS: R36.2 U30.12(RBIAS)
PRG1_RGMII1_RD0: R192.1 ; also on sheet 9
PRG1_RGMII1_RD0_R: R37.1 R38.2 R192.2 U30.33(RX_D0/SGMII_COP)
PRG1_RGMII1_RD1: R193.1 ; also on sheet 9
PRG1_RGMII1_RD1_R: R193.2 U30.34(RX_D1/SGMII_CON)
PRG1_RGMII1_RD2: R195.1 ; also on sheet 9
PRG1_RGMII1_RD2_R: R39.2 R40.1 R195.2 U30.35(RX_D2/SGMII_SOP)
PRG1_RGMII1_RD3: R197.1 ; also on sheet 9
PRG1_RGMII1_RD3_R: R197.2 U30.36(RX_D3/SGMII_SON)
PRG1_RGMII1_REF_CLK: R186.1 ; also on sheet 9
PRG1_RGMII1_RESET#: U30.43(RESET_N) U33.4(Y)
PRG1_RGMII1_RX_CTL: R200.1 ; also on sheet 9
PRG1_RGMII1_RX_CTL_R: R47.1 R200.2 R201.2 U30.38(RX_CTRL)
PRG1_RGMII1_RXC: R191.1 ; also on sheet 9
PRG1_RGMII1_RXC_R: R191.2 U30.32(RX_CLK)
PRG1_RGMII1_TD0: R189.1 ; also on sheet 9
PRG1_RGMII1_TD0_R: R189.2 U30.28(TX_D0/SGMII_SIN)
PRG1_RGMII1_TD1: R188.1 ; also on sheet 9
PRG1_RGMII1_TD1_R: R188.2 U30.27(TX_D1/SGMII_SIP)
PRG1_RGMII1_TD2: R187.1 ; also on sheet 9
PRG1_RGMII1_TD2_R: R187.2 U30.26(TX_D2)
PRG1_RGMII1_TD3: R183.1 ; also on sheet 9
PRG1_RGMII1_TD3_R: R183.2 U30.25(TX_D3)
PRG1_RGMII1_TX_CTL: R199.1 ; also on sheet 9
PRG1_RGMII1_TX_CTL_R: R199.2 U30.37(TX_CTRL)
PRG1_RGMII1_TXC: R190.1 ; also on sheet 9
PRG1_RGMII1_TXC_R: R190.2 U30.29(GTX_CLK)
PRG1_RGMII1_XIN: R184.2 R186.2 U30.15(X_I)
PRG1_RGMII1_XOUT: R185.2 U30.14(X_O)
PRG1_RGMII_INT#: U30.44(INT/PWDN) ; also on sheet 8 16
SOC_PORZ_OUT: U4.1(A) U33.1(A) ; also on sheet 8 13 16 22
N23035325: J21.B12 R65.2
N23036294: C46.2 R75.1 Y2.2
N23036296: C45.2 R74.1 Y2.1
N23045041: C142.2 R184.1 Y3.2
N23045043: C143.2 R185.1 Y3.1
N23046007: J20.A12 R27.2
N23108220: TP14.1(TP) U5.13(VDDA1P8) U5.48(VDDA1P8)
N23109761: TP13.1(TP) U30.13(VDDA1P8) U30.48(VDDA1P8)

Not connected (* = marked no-connect by the designer): J20 A9(VCC1)*; J21 B9(VCC2)*; U5 20(JTAG_CLK)* 21(JTAG_TDO)* 22(JTAG_TMS)* 23(JTAG_TDI)*; U30 20(JTAG_CLK)* 21(JTAG_TDO)* 22(JTAG_TMS)* 23(JTAG_TDI)*

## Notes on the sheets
sheet 14
- PRG0 GB_ETHERNET RGMII 2
- Silk Screen for J21 TOP :
  "PRG0_RGMII2"
- PCB Note:  Route signals as 100-ohm differential
- RJ45
- RESET LOGIC
- RJ45-LED
- FUNCTION
- YELLOW
- ACTIVITY
- ORANGE
- 1000Mbps Speed
- GREEN
- 100Mbps Speed
- SPEED AND ACTIVITY LED DRIVERS
- PHY ADD = 00011
- Auto_neg = Enabled
  ANEGsel 10/100/1000
- RGMII Clock Skew TX = 0ns
  RGMII Clock Skew RX = 2ns
sheet 15
- PRG1 GB_ETHERNET RGMII 1
- Silk Screen for J20 BOTTOM :
  "PRG1_RGMII1"
- PCB Note:  Route signals as 100-ohm differential
- RJ45
- RESET LOGIC
- RJ45-LED
- FUNCTION
- YELLOW
- ACTIVITY
- ORANGE
- 1000Mbps Speed
- SPEED AND ACTIVITY LED DRIVERS
- GREEN
- 100Mbps Speed
- PHY ADD = 01100
- Auto_neg = Enabled
  ANEGsel 10/100/1000
- RGMII Clock Skew TX = 0ns
  RGMII Clock Skew RX = 2ns
